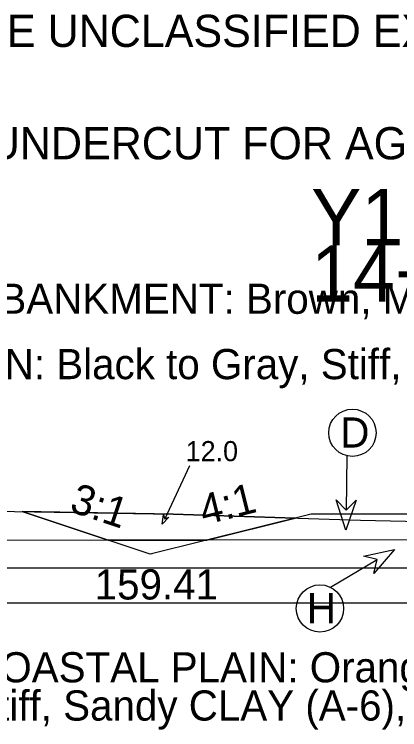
# Model space of a CAD drawing. Extents: x -516 to 303, y -10 to 5017.
# Drawn here: x 125.24 to 144.4, y 3993.69 to 4029.26 of the extents above; entities that cross this region are included whole.
import ezdxf

# ---------------------------------------------------------------- set-up
doc = ezdxf.new("R2010")
doc.units = 0
for name, color, linetype in [('Exist Cross Section Cell', 7, 'Continuous'), ('Exist XS Ground Line', 7, 'Continuous'), ('Misc Plan Tools Cell', 7, 'Continuous'), ('Prop CMT Slope Grass', 7, 'Continuous'), ('Prop Road Sect_ Material - Bubble + Leader + Bubble Tx', 7, 'Continuous'), ('Prop Road Sect_ Material - Contact (General - Major)', 7, 'Continuous'), ('Prop Road Sect_ Material - Contact (General - Minor)', 7, 'Continuous'), ('Prop Road Sect_ Material - Tx (Composite Desc)', 7, 'Continuous'), ('Prop Road Sect_ Misc - Drafting Aid (Tx - small)', 7, 'Continuous'), ('Prop Road Sect_ Recs - UC Shallow (Tx)', 7, 'Continuous'), ('Prop Road Sect_ Recs - UUC (Outline)', 7, 'Continuous'), ('Prop Road Sect_ Recs - UUC (pattern)', 7, 'Continuous'), ('Prop Road Sect_ Recs - UUC (Tx)', 7, 'Continuous'), ('Prop XS Ditch Standard Text', 7, 'Continuous'), ('Prop XS Side Slope Text', 7, 'Continuous'), ('Scratch_Level_0', 7, 'Continuous')]:
    doc.layers.add(name, color=color, linetype=linetype)

msp = doc.modelspace()

# ---------------------------------------------------------------- linework, layer by layer
at = {"layer": 'Exist Cross Section Cell'}
msp.add_line((0, 4000), (150, 4000), dxfattribs=at)
at = {"layer": 'Exist XS Ground Line'}
msp.add_lwpolyline([(123.254, 4004.569), (133.137, 4004.41), (142.46, 4004.107), (147.662, 4003.991), (148.141, 4003.939), (148.466, 4003.921), (150, 4003.846), (151.391, 4003.779), (154.388, 4003.604), (155.624, 4003.528), (157.479, 4003.418), (159.844, 4003.281), (160.736, 4003.234), (161.059, 4003.218), (161.701, 4003.181), (162.102, 4003.161), (173.298, 4003.043)], dxfattribs=at)
at = {"layer": 'Misc Plan Tools Cell'}
for points in [[(142.242, 4005.097), (141.722, 4003.604), (141.242, 4005.11), (141.735, 4004.604)], [(142.604, 4002.322), (144.15, 4002.652), (143.112, 4001.46), (143.289, 4002.145)]]:
    msp.add_lwpolyline(points, close=True, dxfattribs=at)
at = {"layer": 'Prop CMT Slope Grass'}
for p, q in [((132, 4002.411), (125.639, 4004.531)), ((140, 4004.411), (132, 4002.411)), ((146, 4004.408), (140, 4004.411))]:
    msp.add_line(p, q, dxfattribs=at)
at = {"layer": 'Prop Road Sect_ Material - Bubble + Leader + Bubble Tx'}
for p, q in [((141.77, 4007.308), (141.735, 4004.604)), ((140.958, 4000.772), (143.289, 4002.145))]:
    msp.add_line(p, q, dxfattribs=at)
for centre in [(142.055, 4008.449), (140.439, 3999.714)]:
    msp.add_circle(centre, 1.176, dxfattribs=at)
at = {"layer": 'Prop Road Sect_ Material - Contact (General - Major)'}
msp.add_line((162.764, 4003.154), (77.352, 4003.036), dxfattribs=at)
at = {"layer": 'Prop Road Sect_ Material - Contact (General - Minor)'}
msp.add_line((115.068, 4001.737), (187.085, 4001.737), dxfattribs=at)
at = {"layer": 'Prop Road Sect_ Misc - Drafting Aid (Tx - small)'}
msp.add_line((133.955, 4006.812), (132.725, 4004.174), dxfattribs=at)
msp.add_lwpolyline([(132.925, 4004.247), (132.598, 4003.901), (132.652, 4004.374), (132.725, 4004.174)], close=True, dxfattribs=at)
at = {"layer": 'Prop Road Sect_ Recs - UUC (Outline)'}
msp.add_lwpolyline([(125.639, 4004.531), (133.137, 4004.41), (139.209, 4004.213), (134.82, 4003.116), (129.906, 4003.109)], close=True, dxfattribs=at)
at = {"layer": 'Prop Road Sect_ Recs - UUC (pattern)'}
msp.add_lwpolyline([(129.906, 4003.109), (134.82, 4003.116), (139.209, 4004.213), (133.137, 4004.41), (125.639, 4004.531), (129.906, 4003.109)], dxfattribs=at)

# ---------------------------------------------------------------- texts
at = {"layer": 'Exist Cross Section Cell'}
for s, p in [('Y1', (140, 4017.779)), ('14+00.00 / 1', (140, 4014.979))]:
    msp.add_text(s, height=2.8, dxfattribs=at).set_placement(p)
at = {"layer": 'Prop Road Sect_ Material - Tx (Composite Desc)'}
for s, p in [('ROADWAY EMBANKMENT: Brown, Medium Stiff to Stiff, Silty CLAY (A-7-6), Highly Plastic, Moist', (110.569, 4014.367)), ('COASTAL PLAIN: Black to Gray, Stiff, Sandy SILT (A-4), Moist (Black Creek Formation)', (110.494, 4011.117)), ('D', (141.45, 4007.717)), ('H', (139.786, 3998.982)), ('COASTAL PLAIN: Orange-Brown and Gray, Soft to Medium ', (123.1, 3996.04)), ('Stiff, Sandy CLAY (A-6), Moist to Wet (Black Creek Formation)', (123.1, 3994.139))]:
    msp.add_text(s, height=1.5, dxfattribs=at).set_placement(p)
at = {"layer": 'Prop Road Sect_ Misc - Drafting Aid (Tx - small)'}
msp.add_text('12.0', height=1, dxfattribs=at).set_placement((133.763, 4007.039))
at = {"layer": 'Prop Road Sect_ Recs - UC Shallow (Tx)'}
msp.add_text('END SHALLOW UNDERCUT FOR AGGREGATE SUBGRADE', height=1.6, dxfattribs=at).set_placement((107.803, 4022.05))
at = {"layer": 'Prop Road Sect_ Recs - UUC (Tx)'}
msp.add_text('END UNSUITABLE UNCLASSIFIED EXCAVATION-MATERIAL TO BE WASTED', height=1.6, dxfattribs=at).set_placement((107.755, 4027.638))
at = {"layer": 'Prop XS Ditch Standard Text'}
msp.add_text('159.41', height=1.5, dxfattribs=at).set_placement((129.237, 4000.161))
at = {"layer": 'Prop XS Side Slope Text'}
for s, rotation, p in [('3:1', 341.5668, (127.929, 4004.558)), ('4:1', 14.0362, (134.665, 4003.85))]:
    msp.add_text(s, height=1.5, rotation=rotation, dxfattribs=at).set_placement(p)
at = {"layer": 'Scratch_Level_0'}
for s, p in [('LT_Slope_Cut', (125.535, 4004.521)), ('LT_GS_OS_CTL', (139.894, 4004.401)), ('LT_SS_Ditch_Base_Out', (131.821, 4002.401))]:
    msp.add_text(s, height=0.02, dxfattribs=at).set_placement(p)

doc.saveas('drawing.dxf')
